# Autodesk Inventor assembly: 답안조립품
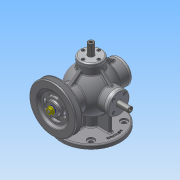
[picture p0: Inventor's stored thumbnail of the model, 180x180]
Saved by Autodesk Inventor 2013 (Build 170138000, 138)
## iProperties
Created: 2016-07
Part Number: 답안조립품
Document SubType Name: Assembly
Designer: Administrator
Author: Administrator
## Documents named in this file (17)
- C:\Users\Administrator\Desktop\360708V1030\답안조립품.iam
- C:\Users\Administrator\Desktop\360708V1030\본체.ipt
- C:\Users\Administrator\Desktop\360708V1030\본체커버.ipt
- C:\Users\Administrator\Desktop\360708V1030\앞커버.ipt
- C:\Users\Administrator\Desktop\360708V1030\뒤커버.ipt
- C:\Users\Administrator\Desktop\360708V1030\베어링- 6202.ipt
- C:\Users\Administrator\Desktop\360708V1030\볼트 M4x0.7.ipt
- C:\Users\Administrator\Desktop\360708V1030\오일실.ipt
- C:\Users\Administrator\Desktop\360708V1030\슬라이드 커버.ipt
- C:\Users\Administrator\Desktop\360708V1030\축.ipt
- C:\Users\Administrator\Desktop\360708V1030\키-4x4.ipt
- C:\Users\Administrator\Desktop\360708V1030\V-벨트풀리.ipt
- C:\Users\Administrator\Desktop\360708V1030\와셔 8x17.ipt
- C:\Users\Administrator\Desktop\360708V1030\너트-M8x1.ipt
- C:\Users\Administrator\Desktop\360708V1030\슬라이드.ipt
- C:\Users\Administrator\Desktop\360708V1030\스프링1.ipt
- C:\Users\Administrator\Desktop\360708V1030\스프링2.ipt
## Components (18 placed, 2 different names)
1. V-벨트풀리:1 — 각도:2
2. M4x0.7x12:17
3. M4x0.7x12:1
4. M4x0.7x12:2
5. M4x0.7x12:3
6. M4x0.7x12:4
7. M4x0.7x12:5
8. M4x0.7x12:6
9. M4x0.7x12:7
10. M4x0.7x12:8
11. M4x0.7x12:9
12. M4x0.7x12:10
13. M4x0.7x12:11
14. M4x0.7x12:12
15. M4x0.7x12:13
16. M4x0.7x12:14
17. M4x0.7x12:15
18. M4x0.7x12:16
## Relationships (1: Angle 1)
- 각도:2 [Angle]: V-벨트풀리:1
